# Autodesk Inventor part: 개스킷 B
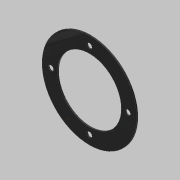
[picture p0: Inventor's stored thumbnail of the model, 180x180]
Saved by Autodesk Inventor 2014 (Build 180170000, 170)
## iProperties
Created: 2019-10
Part Number: 개스킷 B
Material: 고무
Document SubType Name: Modeling
Designer: mduedu
Density: 1 g/cm^3
Appearance: 고무 - 검은색 - 버전 1.1
Author: mduedu
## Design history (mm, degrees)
sketch "스케치1"
  geometry: C1 r 40 at (0, 0); C2 r 27 at (0, 0); 1 further point
  constraints: 2 centre point, 2 coincident
  dimensions: "d0" = 80 diameter of C1; "d1" = 54 diameter of C2
extrude "돌출1" new body sketch "스케치1" distance "d2" = 1; taper "d3" = 0 deg
sketch "스케치2" dims "d4" = 65
  geometry: C1 r 2.25 at (0, 32.5); 2 further points
  constraints: 2 vertical alignment, 1 centre point, 1 coincident, 2 other
  dimensions: "d5" = 4.5 diameter of C1
extrude "돌출2" cut sketch "스케치2" stored distance "d6" = 1; taper "d7" = 0 deg
node "솔리드1"
pattern_circular "원형 패턴1" dims angle "d9" = 360 deg
